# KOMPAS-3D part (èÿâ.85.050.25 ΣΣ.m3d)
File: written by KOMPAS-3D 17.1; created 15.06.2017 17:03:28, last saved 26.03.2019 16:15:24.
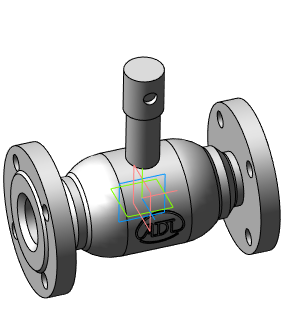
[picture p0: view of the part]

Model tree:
1. Операция без истории:2  (labels: Сталь 20  ГОСТ 1050-88)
